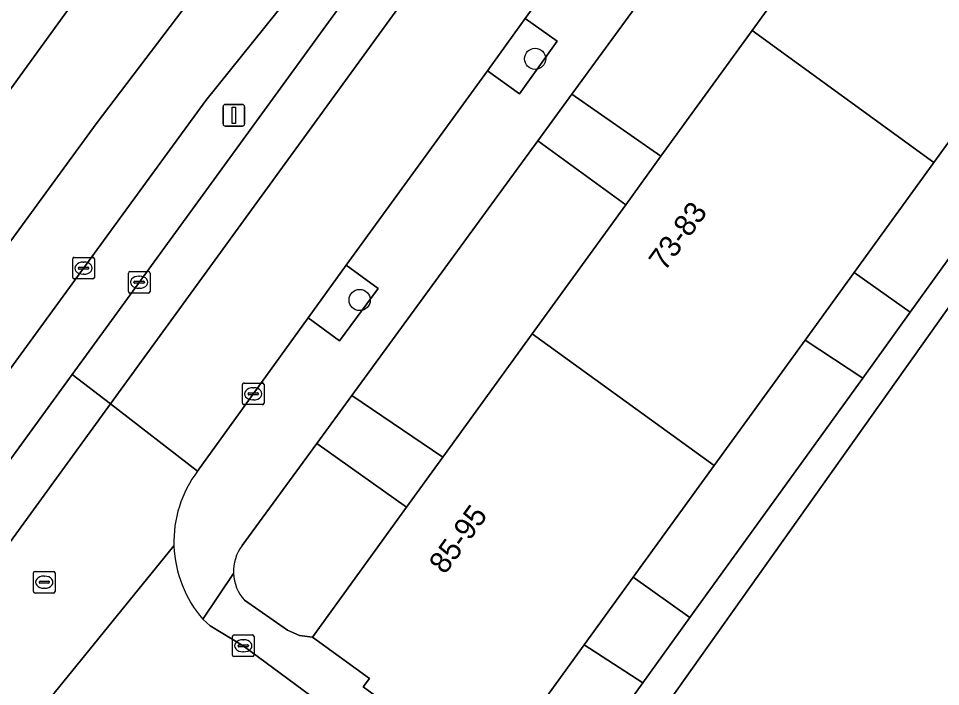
# Model space of a CAD drawing. Extents: x 160102 to 160934, y 382045 to 382923.
# Drawn here: x 160378.27 to 160420.86, y 382523.71 to 382554.58 of the extents above; entities that cross this region are included whole.
import ezdxf

# ---------------------------------------------------------------- set-up
doc = ezdxf.new("R2010")
doc.units = 0
for name, color, linetype in [('IMGEO_Berm_groen', 7, 'Continuous'), ('IMGEO_Boom', 7, 'Continuous'), ('IMGEO_Groenvoorziening', 7, 'Continuous'), ('IMGEO_Haag', 7, 'Continuous'), ('IMGEO_Kolk', 7, 'Continuous'), ('IMGEO_Lichtmast', 7, 'Continuous'), ('IMGEO_Pand', 7, 'Continuous'), ('IMGEO_Pand_nummerreeks', 7, 'Continuous'), ('IMGEO_Parkeervlak_open', 7, 'Continuous'), ('IMGEO_Rijbaan_lokaal_gesloten', 7, 'Continuous'), ('IMGEO_Rijbaan_lokaal_open', 7, 'Continuous'), ('IMGEO_Rioolput', 7, 'Continuous'), ('IMGEO_Voetpad_op_trap', 7, 'Continuous'), ('IMGEO_Voetpad_open', 7, 'Continuous')]:
    doc.layers.add(name, color=color, linetype=linetype)

msp = doc.modelspace()

# ---------------------------------------------------------------- linework, layer by layer
at = {"layer": 'IMGEO_Berm_groen'}
msp.add_lwpolyline([(160381.053, 382555.682), (160397.517, 382576.229), (160400.321, 382579.753), (160415.166, 382598.537), (160407.474, 382604.206), (160403.641, 382598.364), (160398.471, 382590.627), (160389.209, 382576.919), (160373.641, 382555.266), (160334.031, 382500), (160303.993, 382458.495), (160308.576, 382455.458), (160331.775, 382487.414), (160333.573, 382489.91), (160359.615, 382526.075)], close=True, dxfattribs=at)
at = {"layer": 'IMGEO_Boom'}
for centre in [(160402.134, 382552.712), (160394.029, 382541.569)]:
    msp.add_circle(centre, 0.489, dxfattribs=at)
at = {"layer": 'IMGEO_Groenvoorziening'}
for points in [[(160348.458, 382493.72), (160350.205, 382496.123), (160361.434, 382511.566), (160378.783, 382535.426), (160380.751, 382538.133), (160382.565, 382540.628), (160403.031, 382568.775), (160403.351, 382569.215), (160402.251, 382570.369), (160401.769, 382569.723), (160399.985, 382567.333), (160395.724, 382561.753), (160386.921, 382550.786), (160384.016, 382546.8), (160354.986, 382506.975), (160353.792, 382505.333), (160350.149, 382500), (160307.841, 382441.68), (160294.004, 382421.442), (160295.236, 382420.526)], [(160416.492, 382560), (160412.434, 382562.851), (160403.833, 382551.078), (160407.948, 382548.212), (160412.153, 382554.014)], [(160399.927, 382552.158), (160401.414, 382551.096), (160403.149, 382553.526), (160401.681, 382554.574)], [(160427.176, 382551.704), (160424.614, 382553.524), (160420.556, 382547.925), (160416.873, 382542.845), (160419.461, 382541.01)], [(160406.323, 382545.97), (160402.258, 382548.922), (160393.668, 382537.164), (160397.871, 382534.31), (160402, 382540.006)], [(160391.646, 382540.752), (160393.106, 382539.685), (160394.877, 382542.108), (160393.41, 382543.181)], [(160417.265, 382537.967), (160414.605, 382539.716), (160410.402, 382533.918), (160406.67, 382528.769), (160409.286, 382526.908)]]:
    msp.add_lwpolyline(points, close=True, dxfattribs=at)
for points in [[(160472.07, 382537.55), (160437.989, 382564.836), (160403.791, 382516.657), (160410.005, 382512.232), (160410.556, 382511.838), (160413.843, 382516.2), (160417.933, 382521.84), (160420.393, 382520.056), (160422.852, 382518.273), (160425.312, 382516.489), (160427.772, 382514.705), (160430.232, 382512.922), (160432.692, 382511.138), (160435.152, 382509.354), (160437.611, 382507.571), (160440.071, 382505.787), (160442.541, 382503.996), (160439.632, 382500), (160438.441, 382498.363), (160435.401, 382494.048), (160435.774, 382493.781)], [(160396.196, 382531.999), (160392.046, 382534.943), (160388.598, 382530.224)], [(160388.706, 382527.703), (160390.7, 382526.313), (160391.25, 382526.069), (160391.847, 382525.999), (160396.196, 382531.999)], [(160407.104, 382523.884), (160404.398, 382525.635), (160400.201, 382519.844)], [(160402.184, 382517.802), (160403.7, 382519.166), (160407.104, 382523.884)]]:
    msp.add_lwpolyline(points, dxfattribs=at)
for centre, radius, start, end in [((160390.191, 382529.03), 1.991, 143.1472, 182.4712), ((160390.199, 382529.032), 1.999, 182.5326, 221.674)]:
    msp.add_arc(centre, radius, start, end, dxfattribs=at)
at = {"layer": 'IMGEO_Haag'}
msp.add_lwpolyline([(160348.458, 382493.72), (160350.205, 382496.123), (160361.434, 382511.566), (160378.783, 382535.426), (160380.751, 382538.133), (160382.565, 382540.628), (160403.031, 382568.775), (160403.351, 382569.215), (160402.251, 382570.369), (160401.769, 382569.723), (160399.985, 382567.333), (160395.724, 382561.753), (160386.921, 382550.786), (160384.016, 382546.8), (160354.986, 382506.975), (160353.792, 382505.333), (160350.149, 382500), (160307.841, 382441.68), (160294.004, 382421.442), (160295.236, 382420.526)], close=True, dxfattribs=at)
at = {"layer": 'IMGEO_Kolk'}
for p, q in [((160380.775, 382542.615), (160380.775, 382543.467)), ((160380.85, 382543.541), (160381.702, 382543.541)), ((160381.776, 382543.467), (160381.776, 382542.615)), ((160381.034, 382543.035), (160381.034, 382543.047)), ((160381.472, 382542.998), (160381.074, 382542.998)), ((160381.077, 382543.084), (160381.475, 382543.084)), ((160381.263, 382543.321), (160381.288, 382543.321)), ((160381.518, 382543.047), (160381.518, 382543.035)), ((160381.702, 382542.541), (160380.85, 382542.541)), ((160381.286, 382542.761), (160381.261, 382542.761)), ((160383.346, 382541.965), (160383.346, 382542.817)), ((160383.421, 382542.891), (160384.273, 382542.891)), ((160383.834, 382542.671), (160383.859, 382542.671)), ((160384.347, 382542.817), (160384.347, 382541.965)), ((160383.605, 382542.385), (160383.605, 382542.397)), ((160384.043, 382542.348), (160383.645, 382542.348)), ((160383.648, 382542.434), (160384.046, 382542.434)), ((160383.857, 382542.111), (160383.832, 382542.111)), ((160384.089, 382542.397), (160384.089, 382542.385)), ((160384.273, 382541.891), (160383.421, 382541.891)), ((160388.613, 382536.81), (160388.613, 382537.662)), ((160388.688, 382537.736), (160389.54, 382537.736)), ((160389.101, 382537.516), (160389.126, 382537.516)), ((160389.614, 382537.662), (160389.614, 382536.81)), ((160388.872, 382537.23), (160388.872, 382537.242)), ((160389.31, 382537.193), (160388.912, 382537.193)), ((160388.915, 382537.279), (160389.313, 382537.279)), ((160389.356, 382537.242), (160389.356, 382537.23)), ((160389.54, 382536.736), (160388.688, 382536.736)), ((160389.124, 382536.956), (160389.099, 382536.956)), ((160388.153, 382525.172), (160388.153, 382526.024)), ((160388.228, 382526.098), (160389.08, 382526.098)), ((160389.154, 382526.024), (160389.154, 382525.172)), ((160388.412, 382525.592), (160388.412, 382525.604)), ((160388.85, 382525.555), (160388.452, 382525.555)), ((160388.455, 382525.641), (160388.853, 382525.641)), ((160388.641, 382525.878), (160388.666, 382525.878)), ((160388.896, 382525.604), (160388.896, 382525.592)), ((160389.08, 382525.098), (160388.228, 382525.098)), ((160388.664, 382525.318), (160388.639, 382525.318))]:
    msp.add_line(p, q, dxfattribs=at)
for points in [[(160380.775, 382542.615), (160380.775, 382543.467)], [(160380.85, 382543.541), (160381.702, 382543.541)], [(160381.776, 382543.467), (160381.776, 382542.615)], [(160381.702, 382542.541), (160380.85, 382542.541)], [(160383.346, 382541.965), (160383.346, 382542.817)], [(160383.421, 382542.891), (160384.273, 382542.891)], [(160384.347, 382542.817), (160384.347, 382541.965)], [(160384.273, 382541.891), (160383.421, 382541.891)], [(160388.613, 382536.81), (160388.613, 382537.662)], [(160388.688, 382537.736), (160389.54, 382537.736)], [(160389.614, 382537.662), (160389.614, 382536.81)], [(160389.54, 382536.736), (160388.688, 382536.736)], [(160388.153, 382525.172), (160388.153, 382526.024)], [(160388.228, 382526.098), (160389.08, 382526.098)], [(160389.154, 382526.024), (160389.154, 382525.172)], [(160389.08, 382525.098), (160388.228, 382525.098)]]:
    msp.add_lwpolyline(points, dxfattribs=at)
for centre, radius, start, end in [((160380.852, 382543.465), 0.0765, 91.552, 178.448), ((160380.852, 382543.465), 0.0765, 91.552, 178.448), ((160381.7, 382543.465), 0.0765, 1.552, 88.448), ((160381.7, 382543.465), 0.0765, 1.552, 88.448), ((160381.074, 382543.044), 0.0403, 85.8775, 175.7526), ((160381.071, 382543.034), 0.0366, 178.938, 274.7102), ((160381.475, 382543.041), 0.043, 264.8664, 352.4533), ((160381.479, 382543.046), 0.0386, 1.7309, 96.639), ((160380.852, 382542.617), 0.0765, 181.552, 268.448), ((160380.852, 382542.617), 0.0765, 181.552, 268.448), ((160381.7, 382542.617), 0.0765, 271.552, 358.448), ((160381.7, 382542.617), 0.0765, 271.552, 358.448), ((160383.423, 382542.815), 0.0765, 91.552, 178.448), ((160383.423, 382542.815), 0.0765, 91.552, 178.448), ((160384.271, 382542.815), 0.0765, 1.552, 88.448), ((160384.271, 382542.815), 0.0765, 1.552, 88.448), ((160383.645, 382542.394), 0.0403, 85.8775, 175.7526), ((160383.642, 382542.384), 0.0366, 178.938, 274.7102), ((160384.046, 382542.391), 0.043, 264.8664, 352.4533), ((160384.05, 382542.396), 0.0386, 1.7309, 96.639), ((160383.423, 382541.967), 0.0765, 181.552, 268.448), ((160383.423, 382541.967), 0.0765, 181.552, 268.448), ((160384.271, 382541.967), 0.0765, 271.552, 358.448), ((160384.271, 382541.967), 0.0765, 271.552, 358.448), ((160388.69, 382537.66), 0.0765, 91.552, 178.448), ((160388.69, 382537.66), 0.0765, 91.552, 178.448), ((160389.538, 382537.66), 0.0765, 1.552, 88.448), ((160389.538, 382537.66), 0.0765, 1.552, 88.448), ((160388.912, 382537.239), 0.0403, 85.8775, 175.7526), ((160388.909, 382537.229), 0.0366, 178.938, 274.7102), ((160389.313, 382537.236), 0.043, 264.8664, 352.4533), ((160389.317, 382537.241), 0.0386, 1.7309, 96.639), ((160388.69, 382536.812), 0.0765, 181.552, 268.448), ((160388.69, 382536.812), 0.0765, 181.552, 268.448), ((160389.538, 382536.812), 0.0765, 271.552, 358.448), ((160389.538, 382536.812), 0.0765, 271.552, 358.448), ((160388.23, 382526.022), 0.0765, 91.552, 178.448), ((160388.23, 382526.022), 0.0765, 91.552, 178.448), ((160389.078, 382526.022), 0.0765, 1.552, 88.448), ((160389.078, 382526.022), 0.0765, 1.552, 88.448), ((160388.452, 382525.601), 0.0403, 85.8775, 175.7526), ((160388.449, 382525.591), 0.0366, 178.938, 274.7102), ((160388.853, 382525.598), 0.043, 264.8664, 352.4533), ((160388.857, 382525.603), 0.0386, 1.7309, 96.639), ((160388.23, 382525.174), 0.0765, 181.552, 268.448), ((160388.23, 382525.174), 0.0765, 181.552, 268.448), ((160389.078, 382525.174), 0.0765, 271.552, 358.448), ((160389.078, 382525.174), 0.0765, 271.552, 358.448)]:
    msp.add_arc(centre, radius, start, end, dxfattribs=at)
for centre, major_axis, ratio, start_param, end_param in [((160381.262, 382543.041), (-0.387, 0.002), 0.722429, 4.712389, 7.853982), ((160381.287, 382543.041), (-0.39, 0.002), 0.717154, 1.570796, 4.712389), ((160383.833, 382542.391), (-0.387, 0.002), 0.722429, 4.712389, 7.853982), ((160383.858, 382542.391), (-0.39, 0.002), 0.717154, 1.570796, 4.712389), ((160389.1, 382537.236), (-0.387, 0.002), 0.722429, 4.712389, 7.853982), ((160389.125, 382537.236), (-0.39, 0.002), 0.717154, 1.570796, 4.712389), ((160388.64, 382525.598), (-0.387, 0.002), 0.722429, 4.712389, 7.853982), ((160388.665, 382525.598), (-0.39, 0.002), 0.717154, 1.570796, 4.712389)]:
    msp.add_ellipse(centre, major_axis=major_axis, ratio=ratio, start_param=start_param, end_param=end_param, dxfattribs=at)
at = {"layer": 'IMGEO_Lichtmast'}
for p, q in [((160387.822, 382550.605), (160388.612, 382550.605)), ((160388.612, 382550.605), (160387.822, 382550.605)), ((160387.722, 382549.705), (160387.722, 382550.505)), ((160387.722, 382550.505), (160387.722, 382549.705)), ((160388.712, 382550.505), (160388.712, 382549.705)), ((160388.712, 382549.705), (160388.712, 382550.505)), ((160388.612, 382549.605), (160387.822, 382549.605)), ((160387.822, 382549.605), (160388.612, 382549.605))]:
    msp.add_line(p, q, dxfattribs=at)
msp.add_lwpolyline([(160388.142, 382550.48), (160388.292, 382550.48), (160388.292, 382549.73), (160388.142, 382549.73), (160388.142, 382550.48)], dxfattribs=at)
for centre, start, end in [((160387.822, 382550.505), 90, 180), ((160387.822, 382550.505), 90, 180), ((160388.612, 382550.505), 0, 90), ((160388.612, 382550.505), 360, 90), ((160387.822, 382549.705), 180, 270), ((160387.822, 382549.705), 180, 270), ((160388.612, 382549.705), 270, 0), ((160388.612, 382549.705), 270, 0)]:
    msp.add_arc(centre, 0.1, start, end, dxfattribs=at)
at = {"layer": 'IMGEO_Pand'}
for points in [[(160430.709, 382561.932), (160422.306, 382568.021), (160418.113, 382562.237), (160416.492, 382560), (160412.153, 382554.014), (160420.556, 382547.925), (160424.614, 382553.524), (160426.893, 382556.667)], [(160420.556, 382547.925), (160412.153, 382554.014), (160407.948, 382548.212), (160406.323, 382545.97), (160402, 382540.006), (160410.402, 382533.918), (160414.605, 382539.716), (160416.873, 382542.845)], [(160410.402, 382533.918), (160402, 382540.006), (160397.871, 382534.31), (160396.196, 382531.999), (160391.847, 382525.999), (160394.48, 382524.091), (160394.194, 382523.696), (160395.629, 382522.656), (160395.868, 382522.985), (160400.201, 382519.844), (160404.398, 382525.635), (160406.67, 382528.769)]]:
    msp.add_lwpolyline(points, close=True, dxfattribs=at)
at = {"layer": 'IMGEO_Parkeervlak_open'}
msp.add_lwpolyline([(160411.416, 382580.307), (160403.351, 382569.215), (160403.031, 382568.775), (160382.565, 382540.628), (160380.751, 382538.133), (160382.519, 382536.771), (160415.332, 382581.933)], dxfattribs=at)
msp.add_lwpolyline([(160382.519, 382536.771), (160380.751, 382538.133), (160378.783, 382535.426), (160361.434, 382511.566), (160350.205, 382496.123), (160352.026, 382494.8)], close=True, dxfattribs=at)
at = {"layer": 'IMGEO_Rijbaan_lokaal_gesloten'}
for points in [[(160415.166, 382598.537), (160400.321, 382579.753), (160397.517, 382576.229), (160381.053, 382555.682), (160359.615, 382526.075), (160333.573, 382489.91)], [(160417.871, 382596.453), (160400.607, 382574.392), (160381.863, 382549.702), (160349.295, 382505.089), (160332.581, 382482.04), (160323.13, 382467.898), (160316.257, 382457.272), (160313.151, 382452.427), (160309.697, 382447.037), (160301.652, 382434.38), (160279.56, 382400.188)], [(160279.56, 382400.188), (160301.652, 382434.38), (160309.697, 382447.037), (160313.151, 382452.427), (160316.257, 382457.272), (160323.13, 382467.898), (160332.581, 382482.04), (160349.295, 382505.089), (160381.863, 382549.702), (160400.607, 382574.392), (160417.871, 382596.453)], [(160283.59, 382406.211), (160294.004, 382421.442), (160307.841, 382441.68), (160350.149, 382500), (160353.792, 382505.333), (160354.986, 382506.975), (160384.016, 382546.8), (160386.921, 382550.786), (160395.724, 382561.753), (160399.985, 382567.333), (160401.769, 382569.723), (160402.251, 382570.369), (160412.877, 382584.606)]]:
    msp.add_lwpolyline(points, dxfattribs=at)
at = {"layer": 'IMGEO_Rijbaan_lokaal_open'}
msp.add_lwpolyline([(160391.646, 382540.752), (160393.41, 382543.181), (160399.927, 382552.158), (160401.681, 382554.574), (160406.461, 382561.166), (160408.188, 382563.548), (160411.227, 382567.738), (160412.981, 382570.158), (160416.676, 382575.255), (160418.415, 382577.656), (160424.094, 382585.479), (160425.903, 382587.906), (160426.45, 382588.641), (160422.43, 382591.723), (160415.332, 382581.933), (160382.519, 382536.771), (160386.546, 382533.67)], close=True, dxfattribs=at)
for points in [[(160386.546, 382533.67), (160382.519, 382536.771), (160352.026, 382494.8), (160355.311, 382492.415), (160355.389, 382492.523)], [(160378.522, 382521.686), (160385.452, 382530.209)], [(160385.452, 382530.209), (160378.522, 382521.686)], [(160388.654, 382525.598), (160387.119, 382526.518), (160386.785, 382526.833)], [(160434.957, 382491.846), (160434.595, 382492.109), (160408.922, 382510.77), (160400.441, 382516.883), (160388.654, 382525.598)]]:
    msp.add_lwpolyline(points, dxfattribs=at)
for centre, radius, start, end in [((160390.873, 382530.399), 5.424, 142.9114, 182.0057), ((160390.876, 382530.399), 5.427, 182.0101, 221.0827)]:
    msp.add_arc(centre, radius, start, end, dxfattribs=at)
at = {"layer": 'IMGEO_Rioolput'}
for p, q in [((160378.963, 382528.11), (160378.963, 382528.962)), ((160379.038, 382529.036), (160379.89, 382529.036)), ((160379.964, 382528.962), (160379.964, 382528.11)), ((160379.222, 382528.53), (160379.222, 382528.542)), ((160379.66, 382528.493), (160379.262, 382528.493)), ((160379.265, 382528.579), (160379.663, 382528.579)), ((160379.451, 382528.816), (160379.476, 382528.816)), ((160379.706, 382528.542), (160379.706, 382528.53)), ((160379.89, 382528.036), (160379.038, 382528.036)), ((160379.474, 382528.256), (160379.449, 382528.256))]:
    msp.add_line(p, q, dxfattribs=at)
for points in [[(160378.963, 382528.11), (160378.963, 382528.962)], [(160379.038, 382529.036), (160379.89, 382529.036)], [(160379.964, 382528.962), (160379.964, 382528.11)], [(160379.89, 382528.036), (160379.038, 382528.036)]]:
    msp.add_lwpolyline(points, dxfattribs=at)
for centre, radius, start, end in [((160379.04, 382528.96), 0.0765, 91.552, 178.448), ((160379.04, 382528.96), 0.0765, 91.552, 178.448), ((160379.888, 382528.96), 0.0765, 1.552, 88.448), ((160379.888, 382528.96), 0.0765, 1.552, 88.448), ((160379.262, 382528.539), 0.0403, 85.8775, 175.7526), ((160379.259, 382528.529), 0.0366, 178.938, 274.7102), ((160379.663, 382528.536), 0.043, 264.8664, 352.4533), ((160379.667, 382528.541), 0.0386, 1.7309, 96.639), ((160379.04, 382528.112), 0.0765, 181.552, 268.448), ((160379.04, 382528.112), 0.0765, 181.552, 268.448), ((160379.888, 382528.112), 0.0765, 271.552, 358.448), ((160379.888, 382528.112), 0.0765, 271.552, 358.448)]:
    msp.add_arc(centre, radius, start, end, dxfattribs=at)
for centre, major_axis, ratio, start_param, end_param in [((160379.45, 382528.536), (-0.387, 0.002), 0.722429, 4.712389, 7.853982), ((160379.475, 382528.536), (-0.39, 0.002), 0.717154, 1.570796, 4.712389)]:
    msp.add_ellipse(centre, major_axis=major_axis, ratio=ratio, start_param=start_param, end_param=end_param, dxfattribs=at)
at = {"layer": 'IMGEO_Voetpad_op_trap'}
for points in [[(160419.461, 382541.01), (160416.873, 382542.845), (160414.605, 382539.716), (160417.265, 382537.967)], [(160409.286, 382526.908), (160406.67, 382528.769), (160404.398, 382525.635), (160407.104, 382523.884)]]:
    msp.add_lwpolyline(points, close=True, dxfattribs=at)
at = {"layer": 'IMGEO_Voetpad_open'}
for points in [[(160402.258, 382548.922), (160403.833, 382551.078), (160412.434, 382562.851), (160413.97, 382564.954), (160422.539, 382576.683), (160424.126, 382578.857), (160430.115, 382587.054), (160435.406, 382595.933), (160432.912, 382597.37)], [(160424.094, 382585.479), (160418.415, 382577.656), (160419.887, 382576.604), (160418.163, 382574.192), (160416.676, 382575.255), (160412.981, 382570.158), (160414.463, 382569.08), (160412.705, 382566.663), (160411.227, 382567.738), (160408.188, 382563.548), (160409.648, 382562.496), (160407.928, 382560.109), (160406.461, 382561.166), (160401.681, 382554.574), (160403.149, 382553.526), (160401.414, 382551.096), (160399.927, 382552.158), (160393.41, 382543.181), (160394.877, 382542.108), (160393.106, 382539.685), (160391.646, 382540.752), (160386.546, 382533.67)], [(160445.752, 382577.45), (160439.693, 382569.052), (160437.257, 382565.676), (160429.461, 382554.871), (160427.176, 382551.704), (160419.461, 382541.01), (160417.265, 382537.967), (160409.286, 382526.908), (160407.104, 382523.884), (160403.7, 382519.166), (160402.184, 382517.802), (160403.791, 382516.657), (160437.989, 382564.836), (160472.07, 382537.55)], [(160388.598, 382530.224), (160392.046, 382534.943), (160393.668, 382537.164), (160402.258, 382548.922)], [(160386.785, 382526.833), (160388.202, 382528.944)], [(160388.202, 382528.944), (160386.785, 382526.833), (160387.119, 382526.518), (160388.654, 382525.598), (160400.441, 382516.883), (160408.922, 382510.77), (160410.005, 382512.232), (160403.791, 382516.657), (160402.184, 382517.802)], [(160395.868, 382522.985), (160395.629, 382522.656), (160394.194, 382523.696), (160394.48, 382524.091), (160391.847, 382525.999), (160391.25, 382526.069), (160390.7, 382526.313), (160388.706, 382527.703)]]:
    msp.add_lwpolyline(points, dxfattribs=at)
for points in [[(160403.833, 382551.078), (160402.258, 382548.922), (160406.323, 382545.97), (160407.948, 382548.212)], [(160393.668, 382537.164), (160392.046, 382534.943), (160396.196, 382531.999), (160397.871, 382534.31)]]:
    msp.add_lwpolyline(points, close=True, dxfattribs=at)
for centre, radius, start, end in [((160390.873, 382530.399), 5.424, 142.9114, 182.0057), ((160390.876, 382530.399), 5.427, 182.0101, 221.0827), ((160390.191, 382529.03), 1.991, 143.1472, 182.4712), ((160390.199, 382529.032), 1.999, 182.5326, 221.674)]:
    msp.add_arc(centre, radius, start, end, dxfattribs=at)

# ---------------------------------------------------------------- texts
at = {"layer": 'IMGEO_Pand_nummerreeks'}
for s, p in [('73-83', (160408.12, 382542.861)), ('85-95', (160397.967, 382528.854))]:
    msp.add_text(s, height=1, rotation=54.0643, dxfattribs=at).set_placement(p)

doc.saveas('drawing.dxf')
